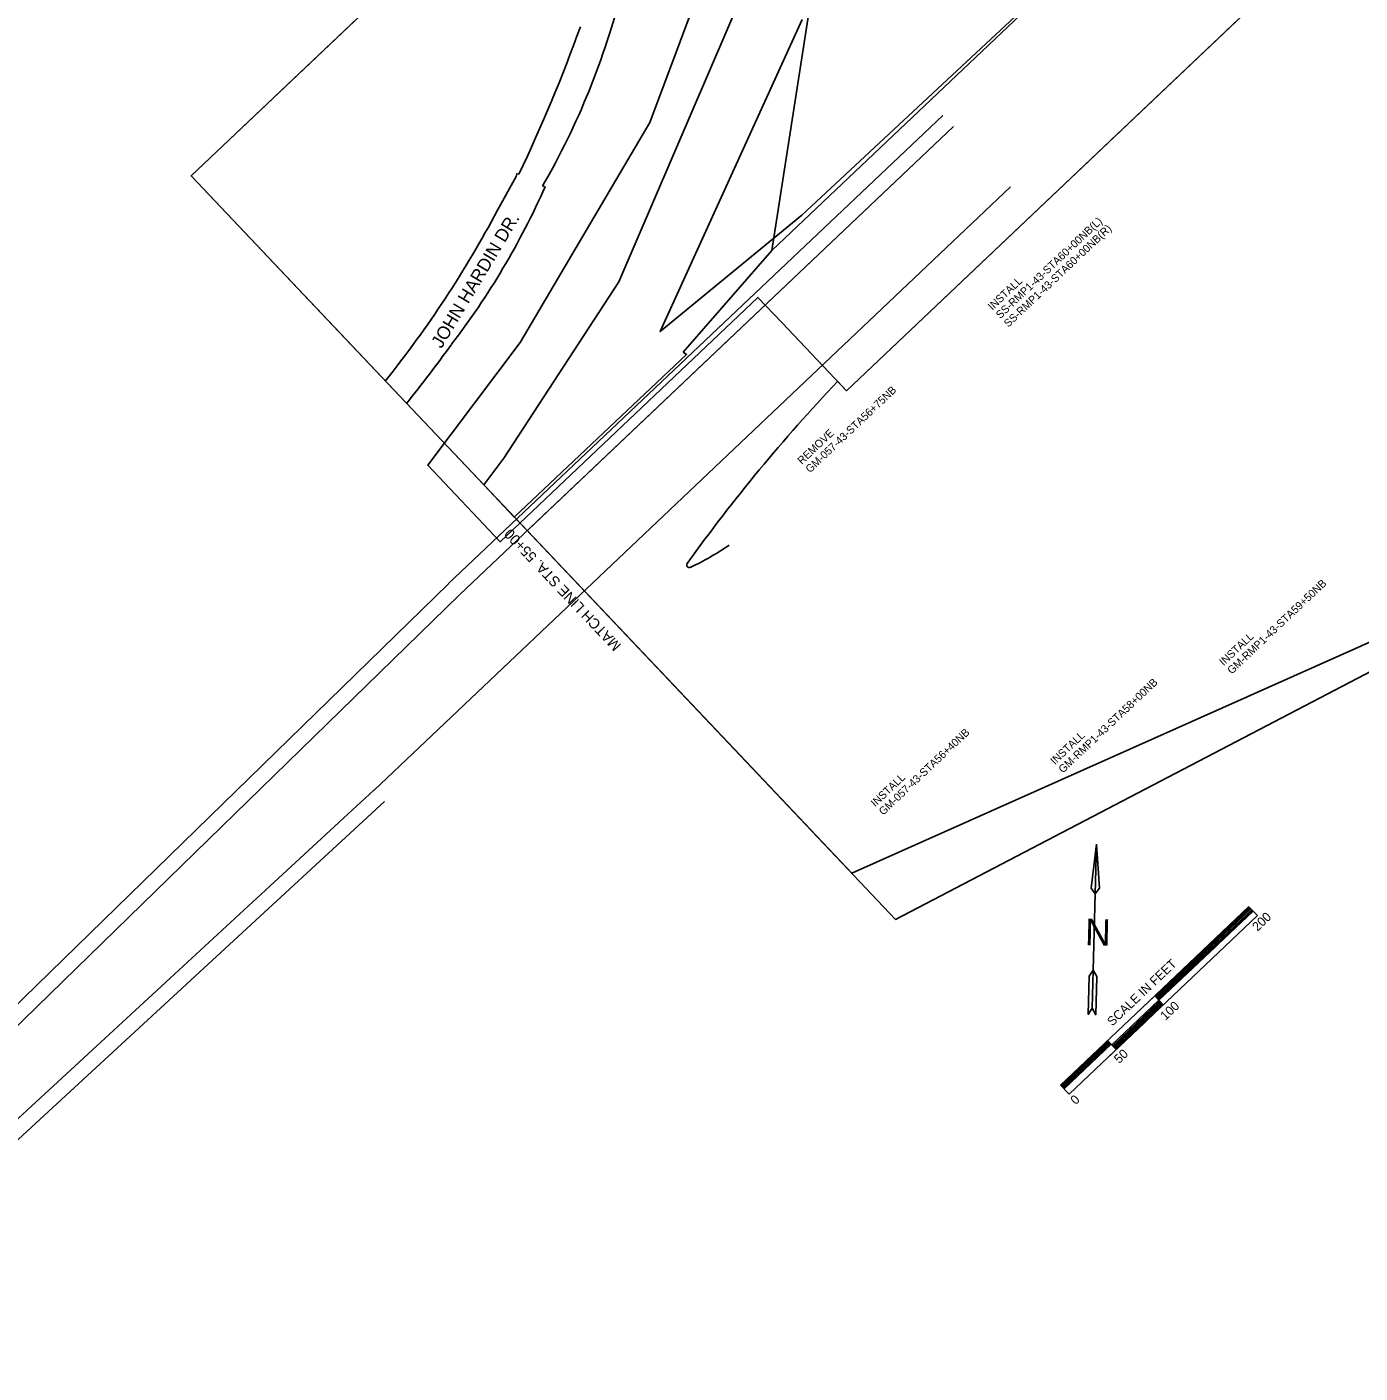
# Model space of a CAD drawing. Extents: x 1289840 to 1295361, y 220865 to 226414.
# Drawn here: x 1291774 to 1292802, y 222460 to 223498 of the extents above; entities that cross this region are included whole.
import ezdxf

# ---------------------------------------------------------------- set-up
doc = ezdxf.new("R2010")
doc.units = 0
for name, color, linetype in [('5', 7, 'Continuous'), ('G-ANNO-TEXT', 7, 'Continuous'), ('Level 10', 7, 'Continuous'), ('Plan Notes', 7, 'Continuous'), ('R_Annotation', 7, 'Continuous'), ('R_No Plot', 7, 'Continuous'), ('R_Proposed Road', 7, 'Continuous'), ('S_EDGE_PAVEMENT', 7, 'Continuous'), ('S_JOINT_LINES', 7, 'Continuous')]:
    doc.layers.add(name, color=color, linetype=linetype)

msp = doc.modelspace()

# ---------------------------------------------------------------- linework, layer by layer
msp.add_lwpolyline([(1292980.7, 223090.1), (1292443.5, 222809.8), (1291900.1, 223383.1), (1292988.8, 224414.9), (1293451.5, 223926.8), (1293499.2, 223784), (1293629.8, 223673.9), (1293562.5, 223543.2), (1293152.7, 223154.8)], close=True)
for points in [[(1292371.4, 223503.8), (1292262, 223263.1), (1292371.2, 223352.9), (1292711, 223669.6)], [(1292782.7, 223574.9), (1292405.6, 223217.5), (1292356.1, 223269.8), (1292337.4, 223289.4), (1292138.6, 223101), (1292082.7, 223160), (1292153.9, 223254.6), (1292254, 223424.4), (1292323.5, 223609.8)]]:
    msp.add_lwpolyline(points)
at = {"layer": '5'}
msp.add_line((1292319, 222941.2), (1292009.4, 223267.8), dxfattribs=at)
at = {"layer": 'G-ANNO-TEXT'}
for p, q in [((1292598.6, 222867.9), (1292594.5, 222833.9)), ((1292594.5, 222833.9), (1292597.5, 222829.4)), ((1292595.9, 222770.5), (1292597.5, 222829.4))]:
    msp.add_line(p, q, dxfattribs=at)
for points in [[(1292598.5, 222867.7), (1292597.5, 222829.4), (1292600.8, 222833.8)], [(1292592.9, 222766), (1292592.1, 222736.5), (1292595.1, 222741.3), (1292595.9, 222770.6)], [(1292595.9, 222770.6), (1292598.7, 222765.8), (1292597.9, 222736.3), (1292595.1, 222741.3)]]:
    msp.add_lwpolyline(points, close=True, dxfattribs=at)
at = {"layer": 'Level 10'}
for p, q in [((1292628.9, 222737.1), (1292716, 222819.7)), ((1292643.9, 222750.3), (1292716.5, 222819.1)), ((1292644.5, 222749.7), (1292717.1, 222818.5)), ((1292645, 222749.1), (1292717.6, 222817.9)), ((1292645.6, 222748.5), (1292718.2, 222817.3)), ((1292646.1, 222748), (1292718.7, 222816.8)), ((1292646.7, 222747.4), (1292719.3, 222816.2)), ((1292722.6, 222812.7), (1292716, 222819.6)), ((1292577.4, 222675.1), (1292722.6, 222812.7)), ((1292570.8, 222682), (1292686.9, 222792.1)), ((1292646.7, 222747.4), (1292690.2, 222788.7)), ((1292610.4, 222713), (1292646.7, 222747.4)), ((1292611, 222712.4), (1292647.2, 222746.8)), ((1292611.5, 222711.8), (1292647.8, 222746.2)), ((1292612.1, 222711.2), (1292648.3, 222745.6)), ((1292612.6, 222710.6), (1292648.9, 222745)), ((1292613.2, 222710.1), (1292649.4, 222744.5)), ((1292650, 222743.9), (1292643.4, 222750.8)), ((1292606.5, 222702.6), (1292635.5, 222730.1)), ((1292571.4, 222681.5), (1292607.7, 222715.9)), ((1292571.9, 222680.9), (1292608.2, 222715.3)), ((1292572.5, 222680.3), (1292608.8, 222714.7)), ((1292573, 222679.7), (1292609.3, 222714.1)), ((1292573.6, 222679.1), (1292609.9, 222713.6)), ((1292613.7, 222709.5), (1292607.1, 222716.4)), ((1292570.8, 222682), (1292599.8, 222709.6)), ((1292577.4, 222675.1), (1292570.8, 222682))]:
    msp.add_line(p, q, dxfattribs=at)
at = {"layer": 'R_No Plot'}
msp.add_lwpolyline([(1292279.8, 223247.1), (1292348.1, 223325.6), (1292381.6, 223540.4), (1292382.9, 223601.3), (1292385.8, 223622.6), (1292406.3, 223723.1), (1292402.3, 223739.1), (1292372.3, 223715.3), (1292366.5, 223689.4), (1292326.7, 223526.6), (1292230, 223301.4), (1292141.3, 223165.4), (1292125.9, 223144.9), (1292149.4, 223120), (1292282.3, 223245.3)], close=True, dxfattribs=at)
msp.add_lwpolyline([(1292254.4, 223718.8), (1291900.1, 223383.1), (1292009.4, 223267.8), (1292319, 222941.2), (1292409.7, 222845.4), (1292893.5, 223061.1), (1293152.7, 223154.8), (1293377.3, 223473.2), (1293437.5, 223540.6)], dxfattribs=at)
at = {"layer": 'R_Proposed Road'}
for p, q in [((1292348.1, 223325.6), (1293228.9, 224160.4)), ((1292405.6, 223217.5), (1292790.6, 223582.4)), ((1292398.7, 223224.8), (1292405.6, 223217.5))]:
    msp.add_line(p, q, dxfattribs=at)
at = {"layer": 'S_EDGE_PAVEMENT'}
for points in [[(1292136.6, 223356.8), (1292150.8, 223382.7), (1292151.4, 223384.8), (1292153, 223384.4)], [(1292173.3, 223374.8), (1292171.3, 223375.4)]]:
    msp.add_lwpolyline(points, dxfattribs=at)
for centre, radius, start, end in [((1293403.8, 222276.1), 1382, 136.6587, 144.2098), ((1292192.7, 223278.1), 217.5, 295.1735, 304.2839), ((1292284.4, 223083.1), 2, 144.1414, 295.4217)]:
    msp.add_arc(centre, radius, start, end, dxfattribs=at)
for centre, major_axis, ratio, start_param, end_param in [((1291655.9, 223672), (194, 562.3), 0.999724, 4.522474, 4.797294), ((1291026.9, 223921.2), (472.5, 1165.6), 0.991851, 4.65319, 4.751097), ((1291625.7, 223618.2), (184.1, 570.6), 0.999448, 4.369872, 4.606187), ((1291384.7, 223757.2), (327.1, 787.5), 0.999008, 4.431493, 4.616727), ((1291276.6, 223847.9), (569.7, 858.3), 0.986709, 4.618399, 4.673972)]:
    msp.add_ellipse(centre, major_axis=major_axis, ratio=ratio, start_param=start_param, end_param=end_param, dxfattribs=at)
at = {"layer": 'S_JOINT_LINES'}
for p, q in [((1292098.8, 223068.7), (1292479.9, 223429.8)), ((1292107.1, 223060), (1292488.2, 223421.1)), ((1292160.3, 223110.4), (1292488.2, 223421.1)), ((1292041.3, 222909.5), (1292532.2, 223374.7)), ((1291633, 222614.8), (1292098.6, 223068.5)), ((1291641.4, 222606.2), (1292107, 223059.9)), ((1291563.3, 222468.8), (1292041.2, 222909.4)), ((1291571.4, 222460), (1292049.4, 222900.6))]:
    msp.add_line(p, q, dxfattribs=at)

# ---------------------------------------------------------------- texts
at = {"layer": 'G-ANNO-TEXT'}
msp.add_text('N', height=20.4, rotation=358.4728, dxfattribs=at).set_placement((1292589.5, 222790))
at = {"layer": 'Level 10'}
for s, height, p in [('200', 7, (1292722.6, 222800.2)), ('SCALE IN FEET', 7.001, (1292610.7, 222727.1)), ('100', 7, (1292651.7, 222731.5)), ('50', 7, (1292616, 222698.2)), ('0', 7, (1292582.4, 222666.5))]:
    msp.add_text(s, height=height, rotation=43.4774, dxfattribs=at).set_placement(p)
at = {"layer": 'Plan Notes'}
for s, height, rotation, p in [('JOHN HARDIN DR.', 10, 59.1164, (1292093.3, 223249.5)), ('MATCH LINE STA. 55+00', 8, 133.4636, (1292232.4, 223021.4))]:
    msp.add_text(s, height=height, rotation=rotation, dxfattribs=at).set_placement(p)
at = {"layer": 'R_Annotation'}
for s, p in [('SS-RMP1-43-STA60+00NB(L)', (1292524.3, 223272.6)), ('SS-RMP1-43-STA60+00NB(R)', (1292530.5, 223266)), ('INSTALL', (1292518.2, 223279.1)), ('GM-057-43-STA56+75NB', (1292377.5, 223153.7)), ('REMOVE', (1292371.3, 223160.2)), ('GM-RMP1-43-STA59+50NB', (1292702.8, 222998.5)), ('INSTALL', (1292696.6, 223005)), ('GM-RMP1-43-STA58+00NB', (1292572.6, 222922.2)), ('GM-057-43-STA56+40NB', (1292434, 222889.7)), ('INSTALL', (1292566.4, 222928.7)), ('INSTALL', (1292427.8, 222896.2))]:
    msp.add_text(s, height=6, rotation=43.4387, dxfattribs=at).set_placement(p)

doc.saveas('drawing.dxf')
